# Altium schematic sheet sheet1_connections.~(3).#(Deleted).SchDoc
size A3; SheetNumber: 1; SheetTotal: 4
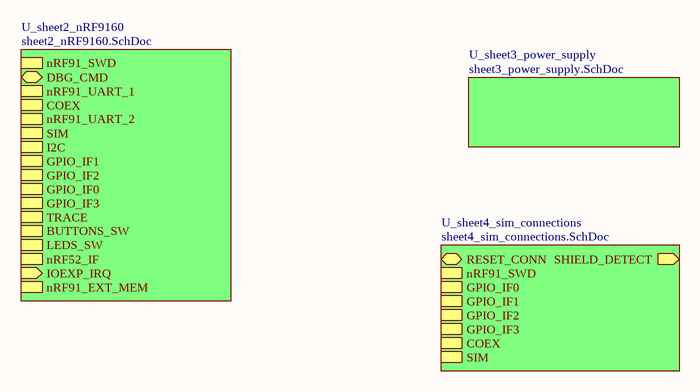
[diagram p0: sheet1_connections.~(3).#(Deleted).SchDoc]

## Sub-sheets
U_sheet2_nRF9160 = sheet2_nRF9160.SchDoc: nRF91_SWD (harness SWD), DBG_CMD (bidir), nRF91_UART_1 (harness UART), COEX (harness COEX), nRF91_UART_2 (harness UART), SIM (harness SIM), I2C (harness I2C), GPIO_IF1 (harness GPIO_IF1), GPIO_IF2 (harness GPIO_IF2), GPIO_IF0 (harness GPIO_IF0), GPIO_IF3 (harness GPIO_IF3), TRACE (harness TRACE), BUTTONS_SW (harness UI), LEDS_SW (harness UI), nRF52_IF (harness nRF_IF), IOEXP_IRQ (in), nRF91_EXT_MEM (harness MEMORY)
U_sheet3_power_supply = sheet3_power_supply.SchDoc: no entries
U_sheet4_sim_connections = sheet4_sim_connections.SchDoc: SHIELD_DETECT (out), RESET_CONN (bidir), nRF91_SWD (harness SWD), GPIO_IF0 (harness GPIO_IF0), GPIO_IF1 (harness GPIO_IF1), GPIO_IF2 (harness GPIO_IF2), GPIO_IF3 (harness GPIO_IF3), COEX (harness COEX), SIM (harness SIM)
